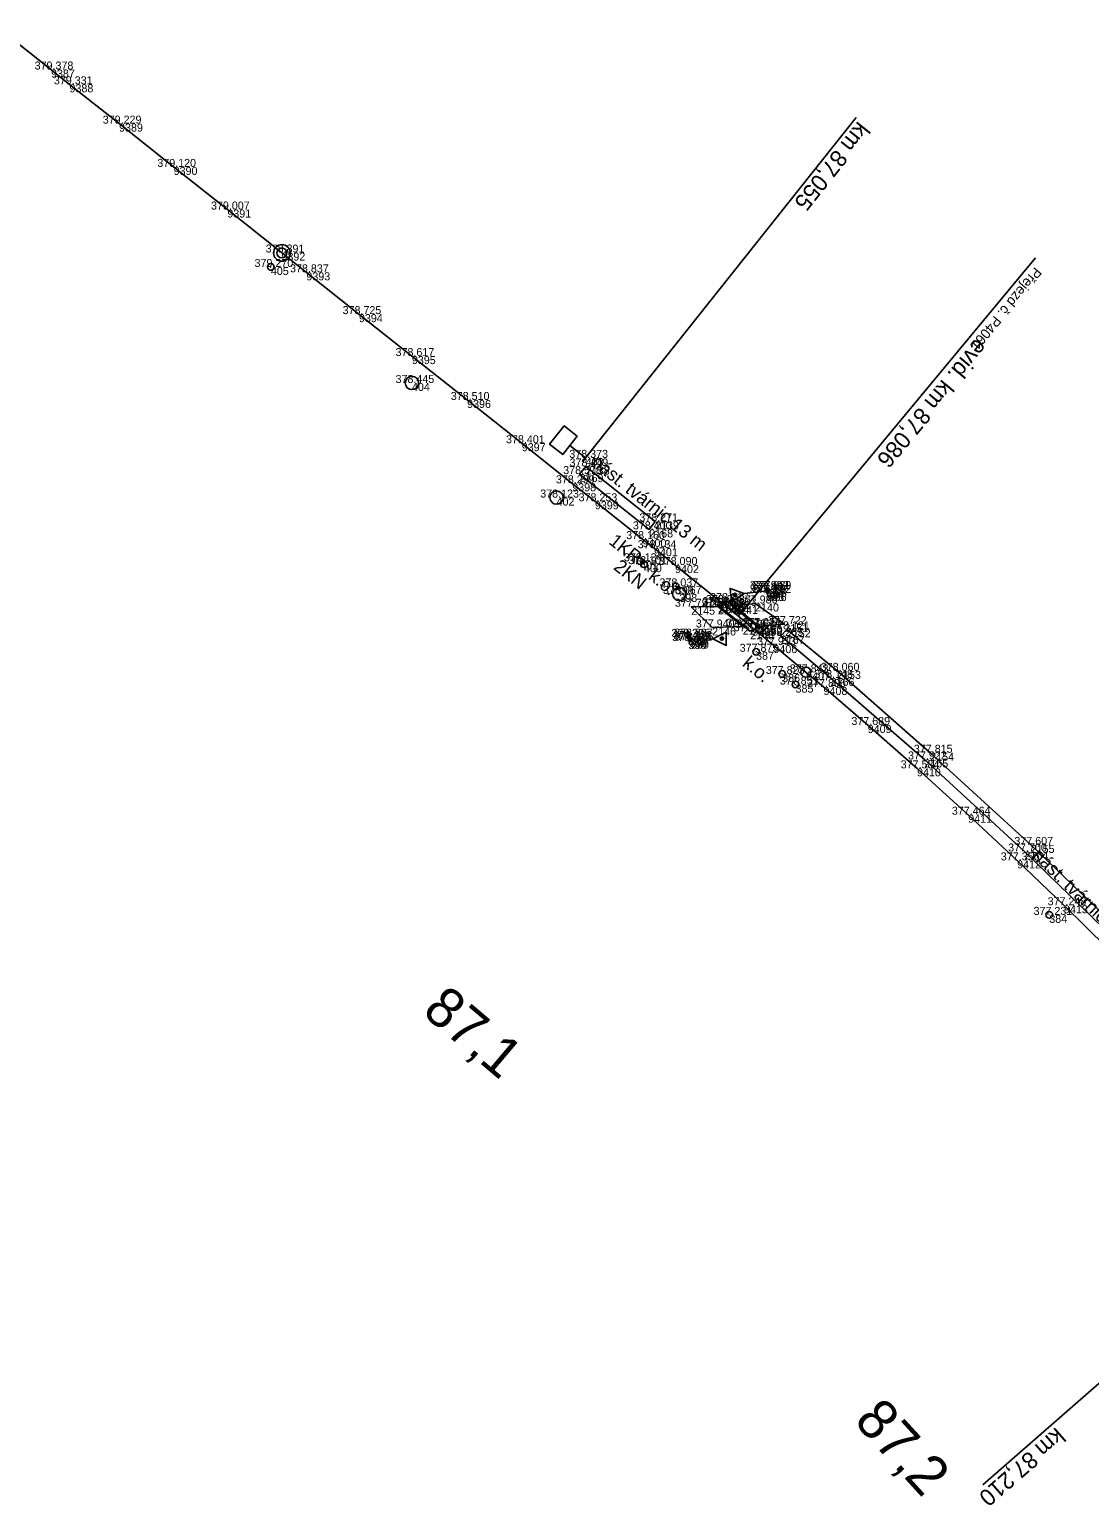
# Model space of a CAD drawing. Extents: x -599511 to -595511, y -1067427 to -1062061.
# Drawn here: x -596884.4 to -596725.5, y -1065469.6 to -1065248.3 of the extents above; entities that cross this region are included whole.
import ezdxf

# ---------------------------------------------------------------- set-up
doc = ezdxf.new("R2010")
doc.units = 0
for name, color, linetype in [('Vrstva 1', 7, 'Continuous'), ('Vrstva 12', 7, 'Continuous'), ('Vrstva 14', 7, 'Continuous'), ('Vrstva 27', 7, 'Continuous'), ('Vrstva 4', 7, 'Continuous'), ('Vrstva 43', 7, 'Continuous'), ('Vrstva 50', 7, 'Continuous'), ('Vrstva 60', 7, 'Continuous'), ('Vrstva 61', 7, 'Continuous'), ('Vrstva 7', 7, 'Continuous')]:
    doc.layers.add(name, color=color, linetype=linetype)

msp = doc.modelspace()

# ---------------------------------------------------------------- linework, layer by layer
at = {"layer": 'Vrstva 1'}
msp.add_lwpolyline([(-596888.71, -1065248.29), (-596881.16, -1065254.29), (-596878.38, -1065256.51), (-596870.95, -1065262.4), (-596862.77, -1065268.89), (-596854.72, -1065275.28), (-596846.61, -1065281.73), (-596842.87, -1065284.7), (-596834.99, -1065290.96), (-596827.05, -1065297.25), (-596818.77, -1065303.83), (-596810.58, -1065310.32), (-596803.01, -1065316.33), (-596799.61, -1065319.02), (-596792.47, -1065324.69), (-596790.75, -1065326.05), (-596787.59, -1065328.58), (-596780.52, -1065334.28), (-596780.05, -1065334.66), (-596775.99, -1065337.98), (-596772.85, -1065340.58), (-596767.94, -1065344.67), (-596765.34, -1065346.86), (-596758.71, -1065352.56), (-596751.32, -1065359.06), (-596743.65, -1065366.01), (-596736.31, -1065372.86), (-596729.29, -1065379.59), (-596722.75, -1065386.03)], dxfattribs=at)
at = {"layer": 'Vrstva 12'}
for points in [[(-596773.92, -1065332.17), (-596773.93, -1065332.76), (-596773.55, -1065332.77), (-596773.53, -1065332.18)], [(-596785.69, -1065339.35), (-596785.3, -1065339.31), (-596785.19, -1065339.89), (-596785.57, -1065339.98)]]:
    msp.add_lwpolyline(points, close=True, dxfattribs=at)
at = {"layer": 'Vrstva 14'}
msp.add_lwpolyline([(-596790.59, -1065322.03), (-596791.47, -1065323.24), (-596801.91, -1065314.94), (-596800.97, -1065313.8)], close=True, dxfattribs=at)
msp.add_lwpolyline([(-596688.36, -1065420.16), (-596688.18, -1065420.03), (-596687.53, -1065420.8), (-596687.34, -1065420.62), (-596688.01, -1065419.84), (-596687.33, -1065419.23), (-596705.98, -1065398.67), (-596706.41, -1065398.26), (-596706.92, -1065397.78), (-596720.57, -1065383.66), (-596734.27, -1065370.54), (-596749.34, -1065356.72), (-596763.3, -1065344.44), (-596770.84, -1065338.22), (-596771.74, -1065339.2), (-596764.28, -1065345.51), (-596750.22, -1065357.72), (-596735.21, -1065371.52), (-596721.61, -1065384.72), (-596707.91, -1065398.76), (-596707.49, -1065399.19), (-596707.13, -1065399.59), (-596688.36, -1065420.16)], dxfattribs=at)
at = {"layer": 'Vrstva 27'}
for p, q in [((-596792.86, -1065327.97), (-596792.78, -1065328.04)), ((-596792.3, -1065328.42), (-596792.22, -1065328.48)), ((-596787.51, -1065331.75), (-596787.44, -1065331.81)), ((-596775.49, -1065341.54), (-596775.41, -1065341.61))]:
    msp.add_line(p, q, dxfattribs=at)
for centre in [(-596792.82, -1065328.01), (-596792.26, -1065328.45), (-596787.48, -1065331.78), (-596775.45, -1065341.58)]:
    msp.add_circle(centre, 0.5, dxfattribs=at)
at = {"layer": 'Vrstva 4'}
for p, q in [((-596778.12, -1065336.23), (-596733.55, -1065282.5)), ((-596773.7, -1065333.21), (-596773.89, -1065331.66)), ((-596778.4, -1065333.2), (-596778.79, -1065332.9)), ((-596785.42, -1065338.91), (-596785.41, -1065340.46)), ((-596780.74, -1065339.43), (-596780.4, -1065339.78))]:
    msp.add_line(p, q, dxfattribs=at)
for points in [[(-596775.07, -1065337.93), (-596779.89, -1065333.98), (-596781.14, -1065334.59), (-596776.34, -1065338.5)], [(-596777.45, -1065337.81), (-596781.17, -1065334.77), (-596785.17, -1065334.83), (-596782.03, -1065337.94)], [(-596771.21, -1065337.44), (-596775.59, -1065334.34), (-596778.73, -1065334.7), (-596775.04, -1065337.74)]]:
    msp.add_lwpolyline(points, close=True, dxfattribs=at)
for points in [[(-596773.79, -1065332.43), (-596777.25, -1065332.85), (-596779.12, -1065334.08), (-596779.36, -1065332.09), (-596777.25, -1065332.85)], [(-596785.41, -1065339.69), (-596781.94, -1065339.65), (-596779.94, -1065338.64), (-596779.91, -1065340.64), (-596781.94, -1065339.65)]]:
    msp.add_lwpolyline(points, dxfattribs=at)
for centre in [(-596778.59, -1065333.05), (-596780.57, -1065339.61)]:
    msp.add_circle(centre, 0.248, dxfattribs=at)
at = {"layer": 'Vrstva 43'}
for centre in [(-596827.04, -1065301.28), (-596805.36, -1065318.46), (-596786.96, -1065332.91)]:
    msp.add_circle(centre, 1, dxfattribs=at)
at = {"layer": 'Vrstva 50'}
for p, q in [((-596771.58, -1065344.88), (-596771.5, -1065344.94)), ((-596731.53, -1065381), (-596731.45, -1065381.07))]:
    msp.add_line(p, q, dxfattribs=at)
for centre in [(-596771.54, -1065344.91), (-596731.49, -1065381.03)]:
    msp.add_circle(centre, 0.5, dxfattribs=at)
at = {"layer": 'Vrstva 60'}
for p, q in [((-596881.16, -1065254.29), (-596881.16, -1065254.29)), ((-596878.38, -1065256.51), (-596878.38, -1065256.51)), ((-596870.95, -1065262.4), (-596870.95, -1065262.4)), ((-596862.77, -1065268.89), (-596862.77, -1065268.89)), ((-596854.72, -1065275.28), (-596854.72, -1065275.28)), ((-596846.61, -1065281.73), (-596846.61, -1065281.73)), ((-596848.19, -1065283.89), (-596848.19, -1065283.89)), ((-596842.87, -1065284.7), (-596842.87, -1065284.7)), ((-596834.99, -1065290.96), (-596834.99, -1065290.96)), ((-596827.05, -1065297.25), (-596827.05, -1065297.25)), ((-596827.04, -1065301.28), (-596827.04, -1065301.28)), ((-596818.77, -1065303.83), (-596818.77, -1065303.83)), ((-596810.58, -1065310.32), (-596810.58, -1065310.32)), ((-596801, -1065312.51), (-596801, -1065312.51)), ((-596800.97, -1065313.8), (-596800.97, -1065313.8)), ((-596803.01, -1065316.33), (-596803.01, -1065316.33)), ((-596801.91, -1065314.94), (-596801.91, -1065314.94)), ((-596805.36, -1065318.46), (-596805.36, -1065318.46)), ((-596799.61, -1065319.02), (-596799.61, -1065319.02)), ((-596790.59, -1065322.03), (-596790.59, -1065322.03)), ((-596792.47, -1065324.69), (-596792.47, -1065324.69)), ((-596791.47, -1065323.24), (-596791.47, -1065323.24)), ((-596790.75, -1065326.05), (-596790.75, -1065326.05)), ((-596792.82, -1065328.01), (-596792.82, -1065328.01)), ((-596792.26, -1065328.45), (-596792.26, -1065328.45)), ((-596787.59, -1065328.58), (-596787.59, -1065328.58)), ((-596787.48, -1065331.78), (-596787.48, -1065331.78)), ((-596786.96, -1065332.91), (-596786.96, -1065332.91)), ((-596779.89, -1065333.98), (-596779.89, -1065333.98)), ((-596773.93, -1065332.76), (-596773.93, -1065332.76)), ((-596773.92, -1065332.17), (-596773.92, -1065332.17)), ((-596773.79, -1065332.43), (-596773.79, -1065332.43)), ((-596773.55, -1065332.77), (-596773.55, -1065332.77)), ((-596773.53, -1065332.18), (-596773.53, -1065332.18)), ((-596785.17, -1065334.83), (-596785.17, -1065334.83)), ((-596781.17, -1065334.77), (-596781.17, -1065334.77)), ((-596781.14, -1065334.59), (-596781.14, -1065334.59)), ((-596780.52, -1065334.28), (-596780.52, -1065334.28)), ((-596780.05, -1065334.66), (-596780.05, -1065334.66)), ((-596778.73, -1065334.7), (-596778.73, -1065334.7)), ((-596775.59, -1065334.34), (-596775.59, -1065334.34)), ((-596782.03, -1065337.94), (-596782.03, -1065337.94)), ((-596777.45, -1065337.81), (-596777.45, -1065337.81)), ((-596776.34, -1065338.5), (-596776.34, -1065338.5)), ((-596775.99, -1065337.98), (-596775.99, -1065337.98)), ((-596775.07, -1065337.93), (-596775.07, -1065337.93)), ((-596775.04, -1065337.74), (-596775.04, -1065337.74)), ((-596771.21, -1065337.44), (-596771.21, -1065337.44)), ((-596770.84, -1065338.22), (-596770.84, -1065338.22)), ((-596785.69, -1065339.35), (-596785.69, -1065339.35)), ((-596785.57, -1065339.98), (-596785.57, -1065339.98)), ((-596785.41, -1065339.69), (-596785.41, -1065339.69)), ((-596785.3, -1065339.31), (-596785.3, -1065339.31)), ((-596785.19, -1065339.89), (-596785.19, -1065339.89)), ((-596772.85, -1065340.58), (-596772.85, -1065340.58)), ((-596771.74, -1065339.2), (-596771.74, -1065339.2)), ((-596775.45, -1065341.58), (-596775.45, -1065341.58)), ((-596771.54, -1065344.91), (-596771.54, -1065344.91)), ((-596767.94, -1065344.67), (-596767.94, -1065344.67)), ((-596763.3, -1065344.44), (-596763.3, -1065344.44)), ((-596769.53, -1065346.5), (-596769.53, -1065346.5)), ((-596765.34, -1065346.86), (-596765.34, -1065346.86)), ((-596764.28, -1065345.51), (-596764.28, -1065345.51)), ((-596758.71, -1065352.56), (-596758.71, -1065352.56)), ((-596750.22, -1065357.72), (-596750.22, -1065357.72)), ((-596749.34, -1065356.72), (-596749.34, -1065356.72)), ((-596751.32, -1065359.06), (-596751.32, -1065359.06)), ((-596743.65, -1065366.01), (-596743.65, -1065366.01)), ((-596735.21, -1065371.52), (-596735.21, -1065371.52)), ((-596734.27, -1065370.54), (-596734.27, -1065370.54)), ((-596736.31, -1065372.86), (-596736.31, -1065372.86)), ((-596729.29, -1065379.59), (-596729.29, -1065379.59)), ((-596731.49, -1065381.03), (-596731.49, -1065381.03))]:
    msp.add_line(p, q, dxfattribs=at)
at = {"layer": 'Vrstva 7'}
for p, q in [((-596801, -1065312.51), (-596760.44, -1065261.48)), ((-596848.23, -1065283.86), (-596848.15, -1065283.92)), ((-596801.47, -1065313.1), (-596800.53, -1065311.92)), ((-596769.57, -1065346.47), (-596769.49, -1065346.53)), ((-596691.76, -1065423.11), (-596741.47, -1065466.46))]:
    msp.add_line(p, q, dxfattribs=at)
msp.add_lwpolyline([(-596801, -1065312.51), (-596803.35, -1065310.64), (-596802.26, -1065309.27), (-596804.22, -1065307.72), (-596806.4, -1065310.46), (-596804.44, -1065312.02), (-596803.35, -1065310.64)], dxfattribs=at)
for centre, radius in [((-596846.54, -1065281.79), 1.25), ((-596846.54, -1065281.79), 0.752), ((-596848.19, -1065283.89), 0.5), ((-596767.99, -1065344.63), 0.75), ((-596769.53, -1065346.5), 0.5)]:
    msp.add_circle(centre, radius, dxfattribs=at)

# ---------------------------------------------------------------- texts
at = {"layer": 'Vrstva 14'}
for s, rotation, p in [('nást. tvárnic 13 m', 321.5713, (-596800.33, -1065313.49)), ('nást. tvárnic. 116 m', 315.8636, (-596734.15, -1065372.31))]:
    msp.add_text(s, height=2, rotation=rotation, dxfattribs=at).set_placement(p)
at = {"layer": 'Vrstva 27'}
for s, rotation, p in [('1KR', 321.3579, (-596797.66, -1065325.29)), ('2KN', 321.3579, (-596796.95, -1065329.11)), ('k.o.', 321.1657, (-596791.71, -1065330.56)), ('k.o.', 320.4752, (-596777.63, -1065343.58))]:
    msp.add_text(s, height=2, rotation=rotation, dxfattribs=at).set_placement(p)
at = {"layer": 'Vrstva 4'}
for s, height, p in [('Přejezd č. P4061', 1.5, (-596733.66, -1065283.81)), ('evid. km 87,086', 2.5, (-596742.42, -1065294.47))]:
    msp.add_text(s, height=height, rotation=230.3233, dxfattribs=at).set_placement(p)
at = {"layer": 'Vrstva 60'}
for s, p in [('9387', (-596881.16, -1065255.49)), ('9388', (-596878.38, -1065257.71)), ('9389', (-596870.95, -1065263.6)), ('9390', (-596862.77, -1065270.09)), ('9391', (-596854.72, -1065276.48)), ('9392', (-596846.61, -1065282.93)), ('405', (-596848.19, -1065285.09)), ('9393', (-596842.87, -1065285.9)), ('9394', (-596834.99, -1065292.16)), ('9395', (-596827.05, -1065298.45)), ('404', (-596827.04, -1065302.48)), ('9396', (-596818.77, -1065305.03)), ('9397', (-596810.58, -1065311.52)), ('403', (-596801, -1065313.71)), ('2138', (-596800.97, -1065315)), ('9398', (-596803.01, -1065317.53)), ('2169', (-596801.91, -1065316.14)), ('402', (-596805.36, -1065319.66)), ('9399', (-596799.61, -1065320.22)), ('2139', (-596790.59, -1065323.23)), ('9400', (-596792.47, -1065325.89)), ('2168', (-596791.47, -1065324.44)), ('9401', (-596790.75, -1065327.25)), ('401', (-596792.82, -1065329.21)), ('400', (-596792.26, -1065329.65)), ('9402', (-596787.59, -1065329.78)), ('399', (-596787.48, -1065332.98)), ('398', (-596786.96, -1065334.11)), ('2142', (-596779.89, -1065335.18)), ('393', (-596773.93, -1065333.96)), ('394', (-596773.92, -1065333.37)), ('397', (-596773.79, -1065333.63)), ('396', (-596773.55, -1065333.97)), ('395', (-596773.53, -1065333.38)), ('2145', (-596785.17, -1065336.03)), ('2144', (-596781.17, -1065335.97)), ('2143', (-596781.14, -1065335.79)), ('9403', (-596780.52, -1065335.48)), ('9404', (-596780.05, -1065335.86)), ('2141', (-596778.73, -1065335.9)), ('2140', (-596775.59, -1065335.54)), ('2146', (-596782.03, -1065339.14)), ('2147', (-596777.45, -1065339.01)), ('2148', (-596776.34, -1065339.7)), ('9405', (-596775.99, -1065339.18)), ('2149', (-596775.07, -1065339.13)), ('2150', (-596775.04, -1065338.94)), ('2151', (-596771.21, -1065338.64)), ('2152', (-596770.84, -1065339.42)), ('391', (-596785.69, -1065340.55)), ('390', (-596785.57, -1065341.18)), ('392', (-596785.41, -1065340.89)), ('388', (-596785.3, -1065340.51)), ('389', (-596785.19, -1065341.09)), ('9406', (-596772.85, -1065341.78)), ('2167', (-596771.74, -1065340.4)), ('387', (-596775.45, -1065342.78)), ('386', (-596771.54, -1065346.11)), ('9407', (-596767.94, -1065345.87)), ('2153', (-596763.3, -1065345.64)), ('385', (-596769.53, -1065347.7)), ('9408', (-596765.34, -1065348.06)), ('2166', (-596764.28, -1065346.71)), ('9409', (-596758.71, -1065353.76)), ('2165', (-596750.22, -1065358.92)), ('2154', (-596749.34, -1065357.92)), ('9410', (-596751.32, -1065360.26)), ('9411', (-596743.65, -1065367.21)), ('2164', (-596735.21, -1065372.72)), ('2155', (-596734.27, -1065371.74)), ('9412', (-596736.31, -1065374.06)), ('9413', (-596729.29, -1065380.79)), ('384', (-596731.49, -1065382.23))]:
    msp.add_text(s, height=1.2, dxfattribs=at).set_placement(p)
at = {"layer": 'Vrstva 61'}
for s, p in [('379.378', (-596883.61, -1065254.29)), ('379.331', (-596880.73, -1065256.51)), ('379.229', (-596873.4, -1065262.4)), ('379.120', (-596865.22, -1065268.89)), ('379.007', (-596857.17, -1065275.28)), ('378.891', (-596848.97, -1065281.73)), ('379.270', (-596850.64, -1065283.89)), ('378.837', (-596845.32, -1065284.7)), ('378.725', (-596837.44, -1065290.96)), ('378.617', (-596829.5, -1065297.25)), ('378.445', (-596829.5, -1065301.28)), ('378.510', (-596821.22, -1065303.83)), ('378.401', (-596812.94, -1065310.32)), ('378.373', (-596803.45, -1065312.51)), ('378.578', (-596804.37, -1065314.94)), ('378.449', (-596803.42, -1065313.8)), ('378.299', (-596805.46, -1065316.33)), ('378.123', (-596807.81, -1065318.46)), ('378.253', (-596802.06, -1065319.02)), ('378.271', (-596792.95, -1065322.03)), ('378.400', (-596793.92, -1065323.24)), ('378.160', (-596794.92, -1065324.69)), ('378.134', (-596793.2, -1065326.05)), ('378.134', (-596795.27, -1065328.01)), ('378.101', (-596794.62, -1065328.45)), ('378.090', (-596790.04, -1065328.58)), ('378.037', (-596789.93, -1065331.78)), ('378.067', (-596789.42, -1065332.91)), ('377.997', (-596776.39, -1065332.76)), ('377.992', (-596776.37, -1065332.17)), ('377.994', (-596776.24, -1065332.43)), ('377.992', (-596775.99, -1065332.77)), ('377.989', (-596775.98, -1065332.18)), ('377.797', (-596787.62, -1065334.83)), ('378.001', (-596783.53, -1065334.77)), ('378.011', (-596783.49, -1065334.59)), ('378.008', (-596782.97, -1065334.28)), ('378.007', (-596782.5, -1065334.66)), ('378.017', (-596782.34, -1065333.98)), ('378.003', (-596781.18, -1065334.7)), ('377.986', (-596778.04, -1065334.34)), ('377.722', (-596773.66, -1065337.44)), ('378.305', (-596788.15, -1065339.35)), ('378.328', (-596787.87, -1065339.69)), ('378.307', (-596787.75, -1065339.31)), ('377.940', (-596784.48, -1065337.94)), ('377.974', (-596779.9, -1065337.81)), ('377.964', (-596778.8, -1065338.5)), ('377.967', (-596778.44, -1065337.98)), ('377.967', (-596777.52, -1065337.93)), ('377.958', (-596777.49, -1065337.74)), ('378.265', (-596774.2, -1065339.2)), ('378.121', (-596773.2, -1065338.22)), ('378.305', (-596788.02, -1065339.98)), ('378.306', (-596787.64, -1065339.89)), ('377.875', (-596777.91, -1065341.58)), ('377.913', (-596775.3, -1065340.58)), ('377.823', (-596773.99, -1065344.91)), ('377.843', (-596770.39, -1065344.67)), ('378.148', (-596766.73, -1065345.51)), ('378.060', (-596765.75, -1065344.44)), ('377.851', (-596771.89, -1065346.5)), ('377.806', (-596767.79, -1065346.86)), ('377.689', (-596761.16, -1065352.56)), ('377.815', (-596751.79, -1065356.72)), ('377.584', (-596753.77, -1065359.06)), ('377.922', (-596752.67, -1065357.72)), ('377.464', (-596746.1, -1065366.01)), ('377.607', (-596736.72, -1065370.54)), ('377.356', (-596738.76, -1065372.86)), ('377.700', (-596737.66, -1065371.52)), ('377.248', (-596731.74, -1065379.59)), ('377.231', (-596733.85, -1065381.03))]:
    msp.add_text(s, height=1.2, dxfattribs=at).set_placement(p)
at = {"layer": 'Vrstva 7'}
for s, height, rotation, p in [('km 87,055', 2.5, 231.5226, (-596760.15, -1065261.92)), ('87,1', 6, 319.8042, (-596825.69, -1065395.81)), ('87,2', 6, 312.3493, (-596760.93, -1065457.01)), ('km 87,210', 2.5, 221.089, (-596730.48, -1065457.74))]:
    msp.add_text(s, height=height, rotation=rotation, dxfattribs=at).set_placement(p)

doc.saveas('drawing.dxf')
